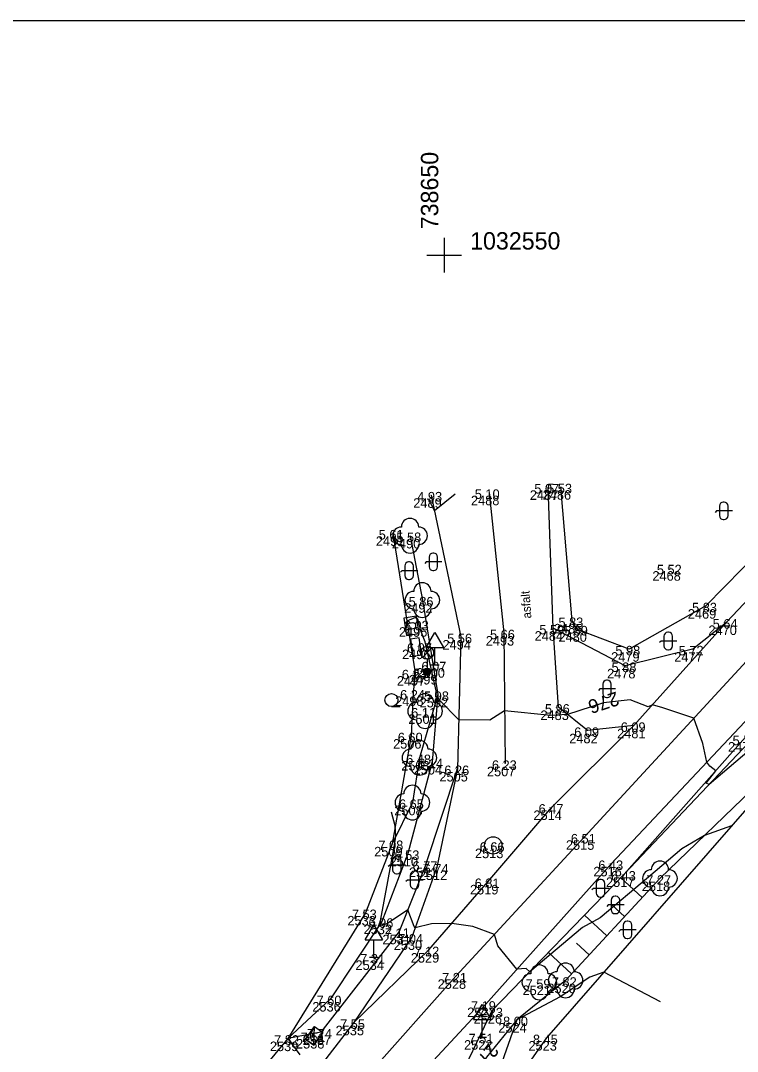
# Model space of a CAD drawing. Extents: x -740053 to -737517, y -1033516 to -1032488.
# Drawn here: x -738674.4 to -738633.1, y -1032595.9 to -1032536.5 of the extents above; entities that cross this region are included whole.
import ezdxf

# ---------------------------------------------------------------- set-up
doc = ezdxf.new("R2010")
doc.units = 0
for name, color, linetype in [('bod-cislo', 7, 'Continuous'), ('bod-oznac', 7, 'Continuous'), ('bod-vyska', 7, 'Continuous'), ('bod-vyska100', 7, 'Continuous'), ('Contours', 7, 'Continuous'), ('Contours highlighted', 7, 'Continuous'), ('Contours text', 7, 'Continuous'), ('ctv-sit', 7, 'Continuous'), ('dopr-zariz', 7, 'Continuous'), ('el-zariz', 7, 'Continuous'), ('nazvy-bud-povr', 7, 'Continuous'), ('objekty-na-kanalizaci', 7, 'Continuous'), ('objekty-na-plynovodu', 7, 'Continuous'), ('osa-komunikace', 7, 'Continuous'), ('ploty', 7, 'Continuous'), ('Ploty-Vjezd', 7, 'Continuous'), ('podezdivka', 7, 'Continuous'), ('Predmety bez rozlišeni', 7, 'Continuous'), ('Rozhrani-ploch', 7, 'Continuous'), ('silnice', 7, 'Continuous'), ('Technické šrafy', 7, 'Continuous'), ('Terenni-hrana', 7, 'Continuous'), ('Znacky-kultury', 7, 'Continuous')]:
    doc.layers.add(name, color=color, linetype=linetype)

# ---------------------------------------------------------------- blocks, each defined once
blk = doc.blocks.new('POINT_DISPLAY')
blk.add_line((0, 0), (0, 0))
blk = doc.blocks.new('p_strom')
for centre, start, end in [((0, 1), 0, 180), ((-1, 0), 90, 270), ((1, 0), 270, 90), ((0, -1), 180, 0)]:
    blk.add_arc(centre, 1, start, end)
at = {"rotation": -180}
blk.add_blockref('POINT_DISPLAY', (0, 0), dxfattribs=at)
blk = doc.blocks.new('po_sasou')
for p, q in [((-1.05, 0.76), (-1.05, -0.73)), ((0.95, 0.76), (-1.05, 0.76)), ((0.95, -0.73), (0.95, 0.76)), ((-1.05, -0.73), (0.95, -0.73))]:
    blk.add_line(p, q)
blk.add_text('U', height=1.09).set_placement((-0.58, -0.53))
blk = doc.blocks.new('el_rozd')
for p, q in [((-1, 1), (-1, 0)), ((1, 1), (-1, 1)), ((-1, 0), (1, 0)), ((1, 0), (1, 1))]:
    blk.add_line(p, q)
blk = doc.blocks.new('el_lamst')
for p, q in [((-0.53, 1.66), (0.53, 2.72)), ((-0.53, 2.72), (0.53, 1.66)), ((0, 1.44), (0, 0.4))]:
    blk.add_line(p, q)
for centre, radius in [((0, 2.19), 0.75), ((0, 0), 0.4), ((0, 0), 0.351), ((0, 0), 0.305), ((0, 0), 0.305), ((0, 0), 0.26), ((0, 0), 0.206), ((0, 0), 0.161), ((0, 0), 0.115), ((0, 0), 0.0619)]:
    blk.add_circle(centre, radius)
blk = doc.blocks.new('d_znacka')
for p, q in [((-1, 2), (0, 3.73)), ((0, 3.73), (1, 2)), ((-1, 2), (1, 2)), ((0, 0), (0, 2)), ((-0.5, 0), (0.5, 0))]:
    blk.add_line(p, q)
blk = doc.blocks.new('po_kansa')
blk.add_circle((0, 0), 1)
blk = doc.blocks.new('po_vpust')
blk.add_line((-0.9, -0.6), (0.9, 0.6))
blk.add_lwpolyline([(-0.9, -0.6), (-0.9, 0.6), (0.9, 0.6), (0.9, -0.6)], close=True)
blk.add_lwpolyline([(-0.9, -0.6), (0.9, 0.6), (-0.9, 0.6), (-0.9, -0.6)])
blk = doc.blocks.new('p_neplod')
for p, q in [((-0.82, 0), (-0.99, -0.18)), ((1, 0), (-0.82, 0)), ((-0.49, 0.56), (-0.49, -0.55)), ((0.05, 1.01), (-0.04, 1.01)), ((0.5, -0.55), (0.5, 0.56)), ((-0.04, -1), (0.05, -1))]:
    blk.add_line(p, q)
for centre, start, end in [((-0.04, 0.56), 90, 180), ((0.05, 0.56), 0, 90), ((-0.04, -0.55), 180, 270), ((0.05, -0.55), 270, 0)]:
    blk.add_arc(centre, 0.45, start, end)
blk = doc.blocks.new('p_zahr')
blk.add_line((0, -0.75), (0.99, -0.75))
blk.add_circle((0, 0), 0.75)
blk = doc.blocks.new('ctvsit')
for p, q in [((0, -2), (0, 2)), ((2, 0), (-2, 0))]:
    blk.add_line(p, q)

msp = doc.modelspace()

# ---------------------------------------------------------------- linework, layer by layer
at = {"layer": 'Contours'}
for points in [[(-738631.65, -1032577.879), (-738634.735, -1032580.5), (-738634.897, -1032580.429), (-738634.351, -1032579.71), (-738634.684, -1032579.432), (-738634.863, -1032579.22), (-738635.095, -1032578.137), (-738635.609, -1032576.68), (-738637.405, -1032576.073), (-738637.992, -1032575.91), (-738638.24, -1032576.027), (-738639.274, -1032575.621), (-738640.806, -1032575.787), (-738642.889, -1032576.462), (-738643.856, -1032576.53), (-738646.508, -1032576.252), (-738647.355, -1032576.784), (-738649.149, -1032576.767), (-738650.279, -1032575.625), (-738650.401, -1032575.804), (-738650.402, -1032575.466), (-738650.472, -1032575.466), (-738650.468, -1032575.314), (-738650.463, -1032575.1), (-738651.093, -1032572.279), (-738651.33, -1032571.65), (-738651.497, -1032571.006), (-738651.651, -1032570.876), (-738652.149, -1032571.08), (-738652.223, -1032571.724)], [(-738633.443, -1032582.889), (-738634.989, -1032583.43), (-738636.304, -1032584.203), (-738638.222, -1032585.833), (-738641.006, -1032588.18), (-738642.023, -1032588.731), (-738645.056, -1032591.285), (-738645.266, -1032591.109), (-738645.802, -1032591.143), (-738646.905, -1032589.795), (-738647.103, -1032589.137), (-738648.349, -1032588.684), (-738649.56, -1032588.509), (-738650.732, -1032588.527), (-738651.658, -1032588.763), (-738651.731, -1032588.678), (-738652.085, -1032587.718), (-738653.321, -1032588.545), (-738653.641, -1032588.625), (-738653.774, -1032588.669), (-738653.655, -1032588.355), (-738653.232, -1032586.083), (-738652.859, -1032583.993), (-738652.772, -1032583.469), (-738652.807, -1032582.875), (-738653.021, -1032582.083)], [(-738637.534, -1032593.014), (-738640.786, -1032591.31), (-738641.6, -1032591.595), (-738643.311, -1032592.736), (-738645.81, -1032594.06), (-738647.551, -1032596.219), (-738648.921, -1032598.112), (-738650.119, -1032599.364), (-738651.743, -1032601), (-738654.371, -1032601.055), (-738655.096, -1032601.214), (-738655.203, -1032601.085), (-738656.466, -1032599.566), (-738656.933, -1032599.437), (-738658.168, -1032599.484), (-738659.098, -1032599.367), (-738659.517, -1032599.488), (-738659.321, -1032598.735), (-738660.061, -1032598.128), (-738660.437, -1032597.631), (-738660.964, -1032597.463), (-738661.163, -1032597.604)]]:
    msp.add_lwpolyline(points, dxfattribs=at)
at = {"layer": 'Contours highlighted'}
msp.add_lwpolyline([(-738649.365, -1032563.758), (-738650.55, -1032564.728), (-738650.778, -1032564.275), (-738650.871, -1032564.072), (-738650.871, -1032564.072), (-738650.969, -1032564.045)], dxfattribs=at)
at = {"layer": 'osa-komunikace'}
for p, q in [((-738647.4, -1032563.67), (-738646.55, -1032571.76)), ((-738646.55, -1032571.76), (-738646.48, -1032579.29)), ((-738631.89, -1032572.65), (-738641.93, -1032583.53)), ((-738641.93, -1032583.53), (-738649.32, -1032591.54)), ((-738649.32, -1032591.54), (-738657.28, -1032600.48))]:
    msp.add_line(p, q, dxfattribs=at)
at = {"layer": 'ploty'}
for p, q in [((-738628.23, -1032576.91), (-738644.09, -1032595.1)), ((-738644.09, -1032595.1), (-738651.25, -1032605.14))]:
    msp.add_line(p, q, dxfattribs=at)
at = {"layer": 'Ploty-Vjezd'}
for p, q in [((-738651.67, -1032574.07), (-738651.77, -1032575.24)), ((-738659, -1032595.13), (-738660.5, -1032596.94))]:
    msp.add_line(p, q, dxfattribs=at)
at = {"layer": 'podezdivka'}
for p, q in [((-738652.96, -1032566.01), (-738651.67, -1032574.07)), ((-738651.77, -1032575.24), (-738651.89, -1032577.7)), ((-738651.89, -1032577.7), (-738652.99, -1032583.91)), ((-738652.99, -1032583.91), (-738654.52, -1032587.89)), ((-738654.52, -1032587.89), (-738659, -1032595.13))]:
    msp.add_line(p, q, dxfattribs=at)
at = {"layer": 'Predmety bez rozlišeni'}
msp.add_line((-738715.011, -1032536.475), (-738610.011, -1032536.475), dxfattribs=at)
at = {"layer": 'Rozhrani-ploch'}
msp.add_line((-738659, -1032595.13), (-738658.31, -1032596.07), dxfattribs=at)
at = {"layer": 'silnice'}
for p, q in [((-738622.06, -1032558.63), (-738633.72, -1032571.15)), ((-738650.74, -1032563.82), (-738649.03, -1032571.99)), ((-738643.72, -1032571.48), (-738644.01, -1032563.36)), ((-738643.4, -1032576.05), (-738643.72, -1032571.48)), ((-738633.72, -1032571.15), (-738639.06, -1032577.1)), ((-738649.03, -1032571.99), (-738649.22, -1032579.59)), ((-738630.27, -1032574.33), (-738640.35, -1032585.06)), ((-738641.74, -1032577.39), (-738643.4, -1032576.05)), ((-738639.06, -1032577.1), (-738643.79, -1032581.81)), ((-738639.06, -1032577.1), (-738641.74, -1032577.39)), ((-738649.22, -1032579.59), (-738650.41, -1032585.27)), ((-738647.47, -1032586.1), (-738643.79, -1032581.81)), ((-738650.41, -1032585.27), (-738651.85, -1032589.3)), ((-738640.35, -1032585.06), (-738647.62, -1032593.17)), ((-738650.88, -1032590.03), (-738647.47, -1032586.1)), ((-738651.85, -1032589.3), (-738655.2, -1032594.22)), ((-738650.88, -1032590.03), (-738655.2, -1032594.22)), ((-738647.62, -1032593.17), (-738655.65, -1032601.81)), ((-738655.2, -1032594.22), (-738658.76, -1032598.82))]:
    msp.add_line(p, q, dxfattribs=at)
at = {"layer": 'Technické šrafy'}
for p, q in [((-738638.579, -1032587.011), (-738639.813, -1032585.869)), ((-738639.597, -1032588.112), (-738640.331, -1032587.433)), ((-738640.616, -1032589.213), (-738641.9, -1032588.025)), ((-738641.635, -1032590.314), (-738642.369, -1032589.635)), ((-738642.653, -1032591.415), (-738643.988, -1032590.181))]:
    msp.add_line(p, q, dxfattribs=at)
at = {"layer": 'Terenni-hrana'}
for p, q in [((-738622.84, -1032557.87), (-738634.92, -1032570.21)), ((-738642.62, -1032571.06), (-738643.27, -1032563.35)), ((-738651.96, -1032566.16), (-738651.25, -1032569.87)), ((-738651.25, -1032569.87), (-738650.36, -1032575.32)), ((-738634.92, -1032570.21), (-738639.34, -1032572.69)), ((-738639.56, -1032573.65), (-738643.72, -1032571.48)), ((-738642.36, -1032571.54), (-738642.62, -1032571.06)), ((-738639.34, -1032572.69), (-738642.36, -1032571.54)), ((-738635.69, -1032572.69), (-738633.72, -1032571.15)), ((-738635.69, -1032572.69), (-738639.56, -1032573.65)), ((-738629.94, -1032574.72), (-738639.62, -1032585.67)), ((-738629.51, -1032574.97), (-738639.62, -1032585.67)), ((-738650.36, -1032575.32), (-738651.42, -1032578.96)), ((-738650.36, -1032575.32), (-738650.69, -1032579.19)), ((-738628.23, -1032576.91), (-738637.56, -1032585.91)), ((-738650.69, -1032579.19), (-738652.09, -1032584.48)), ((-738651.42, -1032578.96), (-738651.82, -1032581.54)), ((-738651.05, -1032585.1), (-738649.22, -1032579.59)), ((-738651.82, -1032581.54), (-738652.99, -1032583.91)), ((-738652.09, -1032584.48), (-738653.59, -1032588.39)), ((-738651.05, -1032585.1), (-738652.58, -1032588.97)), ((-738639.62, -1032585.67), (-738647.25, -1032593.55)), ((-738637.56, -1032585.91), (-738643, -1032591.79)), ((-738653.59, -1032588.39), (-738656.54, -1032592.85)), ((-738652.58, -1032588.97), (-738657.1, -1032594.77)), ((-738643, -1032591.79), (-738645.81, -1032594.06)), ((-738656.54, -1032592.85), (-738659, -1032595.13)), ((-738647.25, -1032593.55), (-738649.47, -1032598.16)), ((-738645.81, -1032594.06), (-738647.18, -1032597.96)), ((-738657.1, -1032594.77), (-738659, -1032595.13))]:
    msp.add_line(p, q, dxfattribs=at)

# ---------------------------------------------------------------- block references
at = {"layer": 'bod-oznac'}
for p in [(-738650.74, -1032563.82), (-738647.4, -1032563.67), (-738644.01, -1032563.36), (-738643.27, -1032563.35), (-738652.96, -1032566.01), (-738651.96, -1032566.16), (-738636.95, -1032568.02), (-738651.25, -1032569.87), (-738634.92, -1032570.21), (-738651.55, -1032571.25), (-738643.72, -1032571.48), (-738642.62, -1032571.06), (-738642.36, -1032571.54), (-738633.72, -1032571.15), (-738649.03, -1032571.99), (-738646.55, -1032571.76), (-738651.37, -1032572.54), (-738639.34, -1032572.69), (-738635.69, -1032572.69), (-738650.54, -1032573.61), (-738639.56, -1032573.65), (-738651.67, -1032574.07), (-738650.98, -1032574), (-738651.77, -1032575.24), (-738650.36, -1032575.32), (-738651.09, -1032576.27), (-738643.4, -1032576.05), (-738641.74, -1032577.39), (-738639.06, -1032577.1), (-738651.89, -1032577.7), (-738651.42, -1032578.96), (-738650.69, -1032579.19), (-738646.48, -1032579.29), (-738649.22, -1032579.59), (-738651.82, -1032581.54), (-738643.79, -1032581.81), (-738652.99, -1032583.91), (-738647.17, -1032584.01), (-738641.93, -1032583.53), (-738652.09, -1032584.48), (-738651.05, -1032585.1), (-738650.41, -1032585.27), (-738640.35, -1032585.06), (-738639.62, -1032585.67), (-738647.47, -1032586.1), (-738637.56, -1032585.91), (-738654.52, -1032587.89), (-738653.59, -1032588.39), (-738652.58, -1032588.97), (-738651.85, -1032589.3), (-738650.88, -1032590.03), (-738654.04, -1032590.45), (-738649.32, -1032591.54), (-738643, -1032591.79), (-738644.51, -1032591.9), (-738656.54, -1032592.85), (-738647.62, -1032593.17), (-738647.25, -1032593.55), (-738645.81, -1032594.06), (-738657.1, -1032594.77), (-738655.2, -1032594.22), (-738659, -1032595.13), (-738657.48, -1032594.98), (-738647.8, -1032595.05), (-738644.09, -1032595.1)]:
    msp.add_blockref('POINT_DISPLAY', p, dxfattribs=at)
at = {"layer": 'ctv-sit', "xscale": 0.5, "yscale": 0.5, "rotation": 180}
msp.add_blockref('ctvsit', (-738650, -1032550), dxfattribs=at)
at = {"layer": 'dopr-zariz', "xscale": 0.5, "yscale": 0.5}
for p in [(-738650.54, -1032573.61), (-738654.04, -1032590.45), (-738647.8, -1032595.05)]:
    msp.add_blockref('d_znacka', p, dxfattribs=at)
at = {"layer": 'el-zariz', "xscale": 0.49999999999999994, "yscale": 0.5000000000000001, "rotation": 98.18565784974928}
msp.add_blockref('el_rozd', (-738651.37, -1032572.54), dxfattribs=at)
at = {"layer": 'el-zariz', "xscale": 0.5, "yscale": 0.5}
msp.add_blockref('el_lamst', (-738650.98, -1032574), dxfattribs=at)
at = {"layer": 'objekty-na-kanalizaci', "xscale": 0.5, "yscale": 0.5}
msp.add_blockref('po_kansa', (-738647.17, -1032584.01), dxfattribs=at)
at = {"layer": 'objekty-na-kanalizaci', "xscale": 0.5, "yscale": 0.4999999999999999, "rotation": 54.563339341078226}
msp.add_blockref('po_vpust', (-738657.48, -1032594.98), dxfattribs=at)
at = {"layer": 'objekty-na-plynovodu', "xscale": 0.5, "yscale": 0.5, "rotation": 98.90987486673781}
msp.add_blockref('po_sasou', (-738651.876, -1032571.332), dxfattribs=at)
at = {"layer": 'Znacky-kultury', "xscale": 0.5, "yscale": 0.5}
for name, p in [('p_neplod', (-738633.891, -1032564.73)), ('p_strom', (-738651.96, -1032566.16)), ('p_neplod', (-738650.62, -1032567.672)), ('p_neplod', (-738652.019, -1032568.179)), ('p_strom', (-738651.25, -1032569.87)), ('p_neplod', (-738637.089, -1032572.232)), ('p_neplod', (-738640.615, -1032574.992)), ('p_zahr', (-738653.032, -1032575.631)), ('p_strom', (-738651.09, -1032576.27)), ('p_strom', (-738651.42, -1032578.96)), ('p_strom', (-738651.82, -1032581.54)), ('p_neplod', (-738652.72, -1032585.141)), ('p_strom', (-738637.56, -1032585.91)), ('p_neplod', (-738651.701, -1032586.007)), ('p_neplod', (-738640.982, -1032586.484)), ('p_neplod', (-738640.126, -1032587.442)), ('p_neplod', (-738639.431, -1032588.878)), ('p_strom', (-738644.51, -1032591.9)), ('p_strom', (-738643, -1032591.79))]:
    msp.add_blockref(name, p, dxfattribs=at)

# ---------------------------------------------------------------- texts
at = {"layer": 'bod-cislo'}
for s, p in [('2488', (-738648.448, -1032564.403)), ('2487', (-738645.058, -1032564.093)), ('2486', (-738644.318, -1032564.083)), ('2489', (-738651.775, -1032564.553)), ('2491', (-738653.929, -1032566.743)), ('2490', (-738653.008, -1032566.893)), ('2468', (-738637.998, -1032568.753)), ('2492', (-738652.298, -1032570.603)), ('2469', (-738635.955, -1032570.943)), ('2495', (-738652.598, -1032571.983)), ('2485', (-738643.668, -1032571.793)), ('2470', (-738634.768, -1032571.883)), ('2494', (-738650.091, -1032572.723)), ('2493', (-738647.598, -1032572.493)), ('2484', (-738644.781, -1032572.213)), ('2480', (-738643.408, -1032572.273)), ('2496', (-738652.418, -1032573.273)), ('2479', (-738640.375, -1032573.423)), ('2477', (-738636.738, -1032573.423)), ('2500', (-738651.588, -1032574.343)), ('2478', (-738640.608, -1032574.383)), ('2497', (-738652.718, -1032574.803)), ('2499', (-738652.015, -1032574.733)), ('2498', (-738652.818, -1032575.973)), ('2502', (-738651.408, -1032576.053)), ('2483', (-738644.448, -1032576.783)), ('2501', (-738652.059, -1032577.003)), ('2481', (-738640.029, -1032577.833)), ('2506', (-738652.938, -1032578.433)), ('2482', (-738642.788, -1032578.123)), ('2476', (-738633.638, -1032578.603)), ('2503', (-738652.468, -1032579.693)), ('2504', (-738651.751, -1032579.923)), ('2505', (-738650.268, -1032580.323)), ('2507', (-738647.528, -1032580.023)), ('2508', (-738652.868, -1032582.273)), ('2514', (-738644.851, -1032582.543)), ('2509', (-738654.025, -1032584.643)), ('2515', (-738642.978, -1032584.263)), ('2510', (-738653.138, -1032585.213)), ('2513', (-738648.218, -1032584.743)), ('2511', (-738652.019, -1032585.833)), ('2516', (-738641.398, -1032585.793)), ('2512', (-738651.458, -1032586.003)), ('2517', (-738640.668, -1032586.403)), ('2519', (-738648.505, -1032586.833)), ('2518', (-738638.608, -1032586.643)), ('2533', (-738655.568, -1032588.623)), ('2532', (-738654.638, -1032589.123)), ('2531', (-738653.549, -1032589.703)), ('2530', (-738652.898, -1032590.033)), ('2534', (-738655.101, -1032591.183)), ('2529', (-738651.915, -1032590.763)), ('2528', (-738650.368, -1032592.273)), ('2521', (-738645.479, -1032592.633)), ('2520', (-738644.048, -1032592.523)), ('2536', (-738657.588, -1032593.583)), ('2527', (-738648.668, -1032593.903)), ('2526', (-738648.298, -1032594.283)), ('2535', (-738656.248, -1032594.953)), ('2524', (-738646.871, -1032594.793)), ('2539', (-738660.035, -1032595.863)), ('2538', (-738658.528, -1032595.713)), ('2537', (-738658.148, -1032595.503)), ('2522', (-738648.848, -1032595.783)), ('2523', (-738645.138, -1032595.833))]:
    msp.add_text(s, height=0.55, dxfattribs=at).set_placement(p)
at = {"layer": 'bod-vyska'}
for s, p in [('5 07', (-738644.799, -1032563.727)), ('5 53', (-738644.059, -1032563.717)), ('4 93', (-738651.542, -1032564.187)), ('5 10', (-738648.228, -1032564.037)), ('5 61', (-738653.762, -1032566.377)), ('5 58', (-738652.749, -1032566.527)), ('5 52', (-738637.739, -1032568.387)), ('5 86', (-738652.039, -1032570.237)), ('5 83', (-738635.709, -1032570.577)), ('5 83', (-738643.409, -1032571.427)), ('5 64', (-738634.522, -1032571.517)), ('6 03', (-738652.313, -1032571.617)), ('5 66', (-738647.352, -1032572.127)), ('5 59', (-738644.509, -1032571.847)), ('5 89', (-738643.149, -1032571.907)), ('5 56', (-738649.819, -1032572.357)), ('6 07', (-738652.133, -1032572.907)), ('5 98', (-738640.129, -1032573.057)), ('5 72', (-738636.479, -1032573.057)), ('6 23', (-738652.433, -1032574.437)), ('6 10', (-738651.782, -1032574.367)), ('6 07', (-738651.303, -1032573.977)), ('5 88', (-738640.349, -1032574.017)), ('6 24', (-738652.533, -1032575.607)), ('5 98', (-738651.149, -1032575.687)), ('6 11', (-738651.892, -1032576.637)), ('5 96', (-738644.189, -1032576.417)), ('6 09', (-738639.823, -1032577.467)), ('6 60', (-738652.666, -1032578.067)), ('6 09', (-738642.503, -1032577.757)), ('5 79', (-738633.379, -1032578.237)), ('6 48', (-738652.183, -1032579.327)), ('6 14', (-738651.492, -1032579.557)), ('6 23', (-738647.243, -1032579.657)), ('6 26', (-738649.983, -1032579.957)), ('6 65', (-738652.596, -1032581.907)), ('6 47', (-738644.553, -1032582.177)), ('6 51', (-738642.693, -1032583.897)), ('7 08', (-738653.779, -1032584.277)), ('6 66', (-738647.946, -1032584.377)), ('6 53', (-738652.853, -1032584.847)), ('6 77', (-738651.813, -1032585.467)), ('6 74', (-738651.173, -1032585.637)), ('6 43', (-738641.113, -1032585.427)), ('6 43', (-738640.383, -1032586.037)), ('7 27', (-738638.349, -1032586.277)), ('6 81', (-738648.233, -1032586.467)), ('7 53', (-738655.309, -1032588.257)), ('6 96', (-738654.353, -1032588.757)), ('7 11', (-738653.408, -1032589.337)), ('7 04', (-738652.639, -1032589.667)), ('7 12', (-738651.708, -1032590.397)), ('7 31', (-738654.829, -1032590.817)), ('7 21', (-738650.109, -1032591.907)), ('7 59', (-738645.299, -1032592.267)), ('7 82', (-738643.789, -1032592.157)), ('7 60', (-738657.342, -1032593.217)), ('7 19', (-738648.448, -1032593.537)), ('7 23', (-738648.039, -1032593.917)), ('7 55', (-738655.989, -1032594.587)), ('8 00', (-738646.599, -1032594.427)), ('7 74', (-738657.889, -1032595.137)), ('7 82', (-738659.789, -1032595.497)), ('7 51', (-738658.269, -1032595.347)), ('7 51', (-738648.589, -1032595.417)), ('8 45', (-738644.879, -1032595.467))]:
    msp.add_text(s, height=0.55, dxfattribs=at).set_placement(p)
at = {"layer": 'bod-vyska100'}
for s, p in [('274 93', (-738650.908, -1032563.853)), ('275 10', (-738647.571, -1032563.703)), ('275 07', (-738644.177, -1032563.393)), ('275 53', (-738643.437, -1032563.383)), ('275 61', (-738653.128, -1032566.043)), ('275 58', (-738652.127, -1032566.193)), ('275 52', (-738637.117, -1032568.053)), ('275 86', (-738651.417, -1032569.903)), ('275 83', (-738635.087, -1032570.243)), ('276 03', (-738651.717, -1032571.283)), ('275 59', (-738643.887, -1032571.513)), ('275 83', (-738642.787, -1032571.093)), ('275 89', (-738642.527, -1032571.573)), ('275 64', (-738633.888, -1032571.183)), ('275 56', (-738649.197, -1032572.023)), ('275 66', (-738646.718, -1032571.793)), ('276 07', (-738651.537, -1032572.573)), ('275 98', (-738639.507, -1032572.723)), ('275 72', (-738635.857, -1032572.723)), ('276 10', (-738651.151, -1032574.033)), ('276 07', (-738650.707, -1032573.643)), ('275 88', (-738639.727, -1032573.683)), ('276 23', (-738651.837, -1032574.103)), ('276 24', (-738651.937, -1032575.273)), ('275 98', (-738650.527, -1032575.353)), ('276 11', (-738651.261, -1032576.303)), ('275 96', (-738643.567, -1032576.083)), ('276 09', (-738641.907, -1032577.423)), ('276 09', (-738639.227, -1032577.133)), ('276 60', (-738652.058, -1032577.733)), ('276 48', (-738651.587, -1032578.993)), ('276 14', (-738650.861, -1032579.223)), ('276 23', (-738646.647, -1032579.323)), ('276 26', (-738649.387, -1032579.623)), ('276 65', (-738651.988, -1032581.573)), ('276 47', (-738643.957, -1032581.843)), ('277 08', (-738653.157, -1032583.943)), ('276 66', (-738647.338, -1032584.043)), ('276 51', (-738642.097, -1032583.563)), ('276 53', (-738652.257, -1032584.513)), ('276 77', (-738651.217, -1032585.133)), ('276 74', (-738650.577, -1032585.303)), ('276 43', (-738640.517, -1032585.093)), ('276 43', (-738639.787, -1032585.703)), ('276 81', (-738647.637, -1032586.133)), ('277 27', (-738637.727, -1032585.943)), ('277 53', (-738654.687, -1032587.923)), ('276 96', (-738653.757, -1032588.423)), ('277 11', (-738652.751, -1032589.003)), ('277 04', (-738652.017, -1032589.333)), ('277 12', (-738651.051, -1032590.063)), ('277 31', (-738654.207, -1032590.483)), ('277 21', (-738649.487, -1032591.573)), ('277 82', (-738643.167, -1032591.823)), ('277 59', (-738644.677, -1032591.933)), ('277 60', (-738656.708, -1032592.883)), ('277 19', (-738647.791, -1032593.203)), ('277 23', (-738647.417, -1032593.583)), ('278 00', (-738645.977, -1032594.093)), ('277 74', (-738657.267, -1032594.803)), ('277 55', (-738655.367, -1032594.253)), ('277 82', (-738659.167, -1032595.163)), ('277 51', (-738657.647, -1032595.013)), ('277 51', (-738647.967, -1032595.083)), ('278 45', (-738644.257, -1032595.133))]:
    msp.add_text(s, height=0.05, dxfattribs=at).set_placement(p)
at = {"layer": 'Contours text'}
for s, rotation, p in [('276', 197.95495, (-738640.074, -1032575.13)), ('278', 234.10316, (-738647.43, -1032595.369))]:
    msp.add_text(s, height=0.8, rotation=rotation, dxfattribs=at).set_placement(p)
at = {"layer": 'ctv-sit'}
msp.add_text('738650', height=1, rotation=90, dxfattribs=at).set_placement((-738650.333, -1032548.5))
msp.add_text('1032550', height=1, dxfattribs=at).set_placement((-738648.5, -1032549.667))
at = {"layer": 'nazvy-bud-povr'}
msp.add_text('asfalt', height=0.5, rotation=94.08789, dxfattribs=at).set_placement((-738644.967, -1032570.916))

doc.saveas('drawing.dxf')
